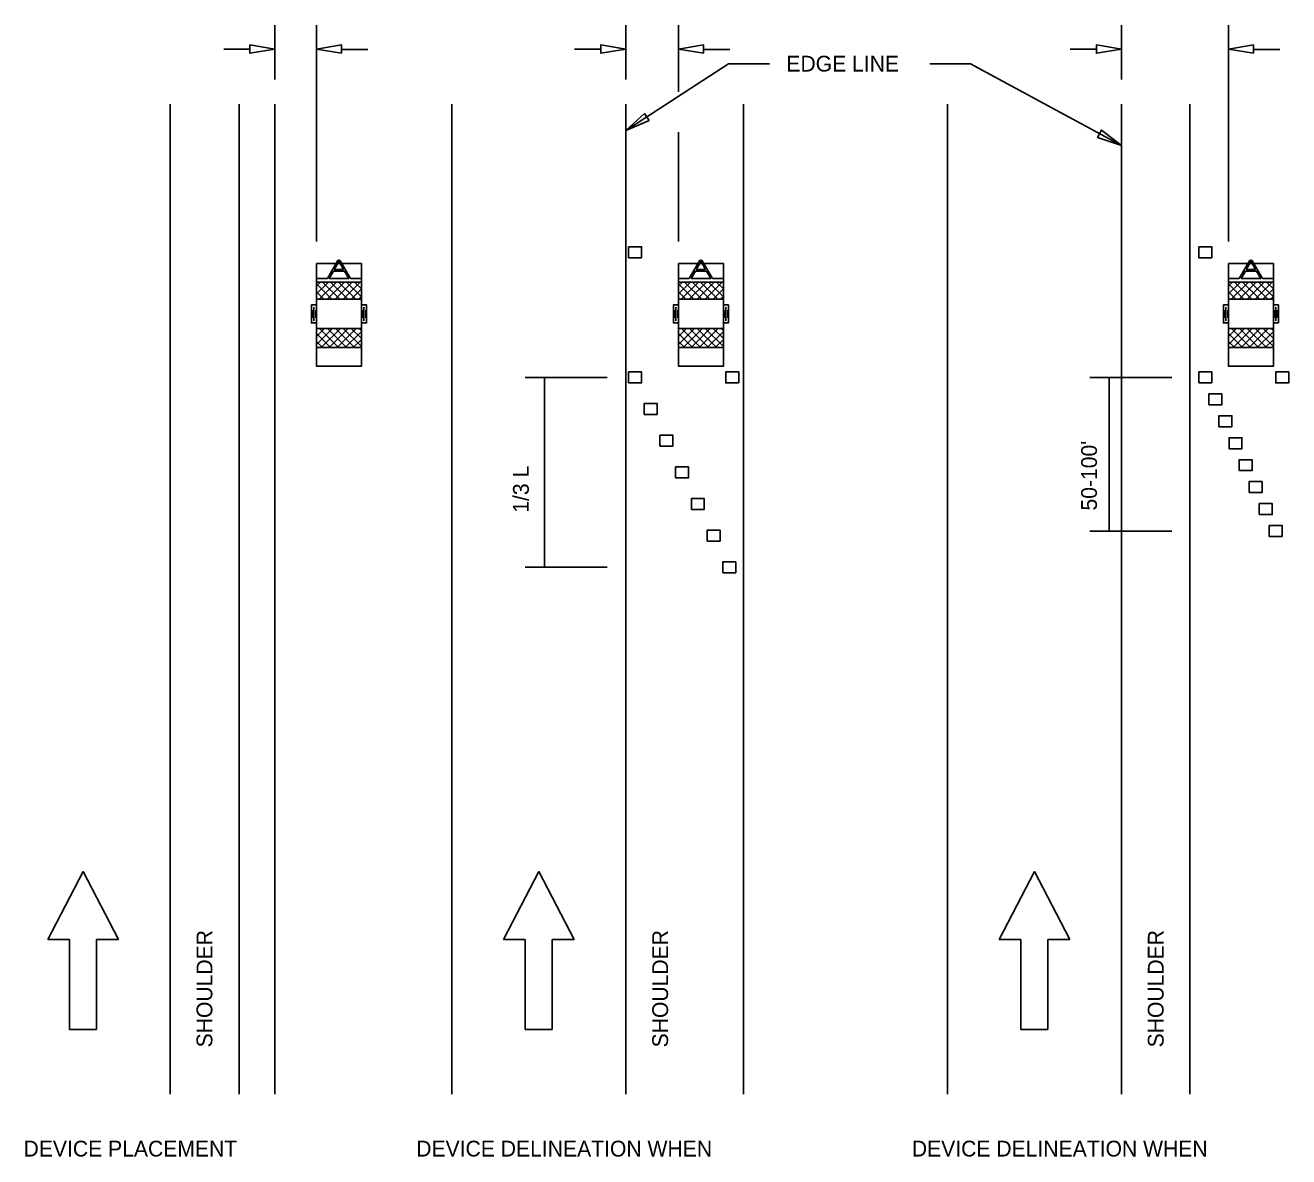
# Model space of a CAD drawing. Extents: x 9 to 25.8, y 6 to 22.7.
# Drawn here: x 14.484 to 19.447, y 11.055 to 15.5 of the extents above; entities that cross this region are included whole.
import ezdxf

# ---------------------------------------------------------------- set-up
doc = ezdxf.new("R2010")
doc.units = 0
for name, color, linetype in [('C-SIGN-FACE_N', 7, 'Continuous'), ('DETL-DIMS', 7, 'Continuous'), ('DETL-LINE', 7, 'Continuous'), ('DETL-NOTE', 7, 'Continuous'), ('SIGN-FACE_P', 7, 'Continuous'), ('SIGN-POST_VSL', 7, 'Continuous'), ('TRAF-MISC', 7, 'Continuous'), ('USER-BORD', 7, 'Continuous')]:
    doc.layers.add(name, color=color, linetype=linetype)

# ---------------------------------------------------------------- blocks, each defined once
blk = doc.blocks.new('DIR2')
at = {"layer": 'USER-BORD'}
for p, q in [((0, 0.0001), (-0.0034, -0.0048)), ((0, 0.0001), (0.0034, -0.0048)), ((-0.0034, -0.0048), (-0.0013, -0.0048)), ((-0.0013, -0.0113), (-0.0013, -0.0048)), ((0.0034, -0.0048), (0.0013, -0.0048)), ((0.0013, -0.0113), (0.0013, -0.0048)), ((-0.0001, -0.0113), (-0.0013, -0.0113)), ((-0.0001, -0.0113), (0.0001, -0.0113)), ((0.0001, -0.0113), (0.0013, -0.0113))]:
    blk.add_line(p, q, dxfattribs=at)

msp = doc.modelspace()

# ---------------------------------------------------------------- linework, layer by layer
at = {"layer": 'C-SIGN-FACE_N'}
for points in [[(15.6282, 14.4912), (15.8043, 14.4912), (15.8043, 14.2335), (15.6282, 14.2335)], [(17.0501, 14.4912), (17.2262, 14.4912), (17.2262, 14.2335), (17.0501, 14.2335)], [(19.2106, 14.4912), (19.3868, 14.4912), (19.3868, 14.2335), (19.2106, 14.2335)]]:
    msp.add_lwpolyline(points, close=True, dxfattribs=at)
at = {"layer": 'DETL-DIMS'}
for p, q in [((15.4647, 15.2868), (15.4647, 15.4998)), ((15.6281, 14.6498), (15.6281, 15.4999)), ((16.8432, 15.2868), (16.8432, 15.4998)), ((17.0501, 15.2388), (17.0501, 15.4999)), ((18.7901, 15.2868), (18.7901, 15.4998)), ((19.2106, 14.6498), (19.2106, 15.4999)), ((15.3667, 15.4065), (15.2633, 15.4065)), ((15.8294, 15.4046), (15.7259, 15.4046)), ((16.7452, 15.4065), (16.6417, 15.4065)), ((17.2513, 15.4046), (17.1479, 15.4046)), ((18.692, 15.4065), (18.5886, 15.4065)), ((19.4119, 15.4046), (19.3084, 15.4046)), ((17.2468, 15.349), (16.8432, 15.086)), ((17.4071, 15.349), (17.2468, 15.349)), ((18.0373, 15.349), (18.1976, 15.349)), ((18.1976, 15.349), (18.7901, 15.0271)), ((17.0501, 14.6498), (17.0501, 15.0799)), ((16.77, 14.1165), (16.4483, 14.1165)), ((16.5241, 14.1165), (16.5241, 13.3704)), ((18.988, 14.1165), (18.6662, 14.1165)), ((18.7421, 14.1165), (18.7421, 13.5129)), ((18.988, 13.5129), (18.6662, 13.5129)), ((16.77, 13.3704), (16.4483, 13.3704))]:
    msp.add_line(p, q, dxfattribs=at)
for points in [[(15.3667, 15.4228), (15.3667, 15.3902), (15.4647, 15.4065)], [(15.7262, 15.3903), (15.7262, 15.4229), (15.6281, 15.4066)], [(16.7452, 15.4228), (16.7452, 15.3902), (16.8432, 15.4065)], [(17.1481, 15.3903), (17.1481, 15.4229), (17.0501, 15.4066)], [(18.692, 15.4228), (18.692, 15.3902), (18.7901, 15.4065)], [(19.3087, 15.3903), (19.3087, 15.4229), (19.2106, 15.4066)], [(16.9342, 15.1258), (16.9164, 15.1532), (16.8432, 15.086)], [(18.6961, 15.0595), (18.7117, 15.0882), (18.7901, 15.0271)]]:
    msp.add_lwpolyline(points, close=True, dxfattribs=at)
at = {"layer": 'DETL-LINE'}
for p, q in [((15.0531, 15.1901), (15.0531, 11.3001)), ((15.3246, 15.1901), (15.3246, 11.3001)), ((15.4647, 11.3001), (15.4647, 15.1901)), ((16.1595, 15.1901), (16.1595, 11.3001)), ((16.8432, 15.1901), (16.8432, 11.3001)), ((17.305, 15.1901), (17.305, 11.3001)), ((18.1063, 15.1901), (18.1063, 11.3001)), ((18.7901, 15.1901), (18.7901, 11.3001)), ((19.0594, 15.1901), (19.0594, 11.3001))]:
    msp.add_line(p, q, dxfattribs=at)
for points in [[(16.8539, 14.6296), (16.8539, 14.5867), (16.9048, 14.5867), (16.9048, 14.6296)], [(19.094, 14.6296), (19.094, 14.5867), (19.145, 14.5867), (19.145, 14.6296)], [(16.8539, 14.095), (16.8539, 14.1379), (16.9048, 14.1379), (16.9048, 14.095)], [(17.2868, 14.095), (17.2868, 14.1379), (17.2358, 14.1379), (17.2358, 14.095)], [(19.094, 14.095), (19.094, 14.1379), (19.145, 14.1379), (19.145, 14.095)], [(19.4473, 14.095), (19.4473, 14.1379), (19.3963, 14.1379), (19.3963, 14.095)], [(19.1336, 14.0088), (19.1336, 14.0517), (19.1845, 14.0517), (19.1845, 14.0088)], [(16.9155, 13.9707), (16.9155, 14.0136), (16.9665, 14.0136), (16.9665, 13.9707)], [(19.1731, 13.9226), (19.1731, 13.9655), (19.2241, 13.9655), (19.2241, 13.9226)], [(16.9772, 13.8463), (16.9772, 13.8892), (17.0281, 13.8892), (17.0281, 13.8463)], [(19.2127, 13.8364), (19.2127, 13.8792), (19.2636, 13.8792), (19.2636, 13.8364)], [(17.0388, 13.722), (17.0388, 13.7649), (17.0898, 13.7649), (17.0898, 13.722)], [(19.2522, 13.7501), (19.2522, 13.793), (19.3032, 13.793), (19.3032, 13.7501)], [(19.2918, 13.6639), (19.2918, 13.7068), (19.3427, 13.7068), (19.3427, 13.6639)], [(17.1005, 13.5977), (17.1005, 13.6405), (17.1514, 13.6405), (17.1514, 13.5977)], [(19.3313, 13.5777), (19.3313, 13.6206), (19.3822, 13.6206), (19.3822, 13.5777)], [(17.1621, 13.4733), (17.1621, 13.5162), (17.2131, 13.5162), (17.2131, 13.4733)], [(19.3709, 13.4915), (19.3709, 13.5344), (19.4218, 13.5344), (19.4218, 13.4915)], [(17.2238, 13.349), (17.2238, 13.3918), (17.2747, 13.3918), (17.2747, 13.349)]]:
    msp.add_lwpolyline(points, close=True, dxfattribs=at)
at = {"layer": 'SIGN-FACE_P'}
for p, q in [((15.6282, 14.5044), (15.6282, 14.4912)), ((15.8043, 14.5044), (15.8043, 14.4912)), ((17.0501, 14.5044), (17.0501, 14.4912)), ((17.2262, 14.5044), (17.2262, 14.4912)), ((19.2107, 14.5044), (19.2107, 14.4912)), ((19.3868, 14.5044), (19.3868, 14.4912))]:
    msp.add_line(p, q, dxfattribs=at)
at = {"layer": 'SIGN-POST_VSL'}
for points in [[(15.6281, 14.5643), (15.8043, 14.5643), (15.8043, 14.1603), (15.6282, 14.1603)], [(17.0501, 14.5643), (17.2262, 14.5643), (17.2262, 14.1603), (17.0501, 14.1603)], [(19.2106, 14.5643), (19.3868, 14.5643), (19.3868, 14.1603), (19.2106, 14.1603)]]:
    msp.add_lwpolyline(points, close=True, dxfattribs=at)
at = {"layer": 'TRAF-MISC'}
for p, q in [((15.6706, 14.5044), (15.7111, 14.5746)), ((15.6978, 14.5397), (15.7133, 14.5665)), ((15.7346, 14.5397), (15.7192, 14.5665)), ((15.7619, 14.5044), (15.7213, 14.5746)), ((17.0925, 14.5044), (17.1331, 14.5746)), ((17.1198, 14.5397), (17.1352, 14.5665)), ((17.1566, 14.5397), (17.1411, 14.5665)), ((17.1838, 14.5044), (17.1433, 14.5746)), ((19.2531, 14.5044), (19.2936, 14.5746)), ((19.2803, 14.5397), (19.2958, 14.5665)), ((19.3171, 14.5397), (19.3017, 14.5665)), ((19.3444, 14.5044), (19.3038, 14.5746)), ((15.6282, 14.5044), (15.6706, 14.5044)), ((15.6774, 14.5044), (15.6944, 14.5338)), ((15.6774, 14.5044), (15.7551, 14.5044)), ((15.6944, 14.5338), (15.738, 14.5338)), ((15.6978, 14.5397), (15.7346, 14.5397)), ((15.7551, 14.5044), (15.738, 14.5338)), ((15.7619, 14.5044), (15.8043, 14.5044)), ((17.0501, 14.5044), (17.0925, 14.5044)), ((17.0993, 14.5044), (17.1164, 14.5338)), ((17.0993, 14.5044), (17.177, 14.5044)), ((17.1164, 14.5338), (17.16, 14.5338)), ((17.1198, 14.5397), (17.1566, 14.5397)), ((17.177, 14.5044), (17.16, 14.5338)), ((17.1838, 14.5044), (17.2262, 14.5044)), ((19.2107, 14.5044), (19.2531, 14.5044)), ((19.2599, 14.5044), (19.2769, 14.5338)), ((19.2599, 14.5044), (19.3376, 14.5044)), ((19.2769, 14.5338), (19.3205, 14.5338)), ((19.2803, 14.5397), (19.3171, 14.5397)), ((19.3376, 14.5044), (19.3205, 14.5338)), ((19.3444, 14.5044), (19.3868, 14.5044)), ((15.6282, 14.4912), (15.6282, 14.4236)), ((15.6282, 14.4444), (15.6749, 14.4912)), ((15.6282, 14.4757), (15.6436, 14.4912)), ((15.6282, 14.4839), (15.6884, 14.4236)), ((15.6282, 14.4526), (15.6572, 14.4236)), ((15.6386, 14.4236), (15.7061, 14.4912)), ((15.6521, 14.4912), (15.7197, 14.4236)), ((15.6698, 14.4236), (15.7374, 14.4912)), ((15.6834, 14.4912), (15.7509, 14.4236)), ((15.7011, 14.4236), (15.7686, 14.4912)), ((15.7146, 14.4912), (15.7822, 14.4236)), ((15.7323, 14.4236), (15.7999, 14.4912)), ((15.7459, 14.4912), (15.8043, 14.4328)), ((15.7636, 14.4236), (15.8043, 14.4643)), ((15.7772, 14.4912), (15.8043, 14.4641)), ((17.0501, 14.4912), (17.0501, 14.4236)), ((17.0501, 14.4444), (17.0969, 14.4912)), ((17.0501, 14.4757), (17.0656, 14.4912)), ((17.0501, 14.4839), (17.1104, 14.4236)), ((17.0501, 14.4526), (17.0792, 14.4236)), ((17.0606, 14.4236), (17.1281, 14.4912)), ((17.0741, 14.4912), (17.1417, 14.4236)), ((17.0918, 14.4236), (17.1594, 14.4912)), ((17.1054, 14.4912), (17.1729, 14.4236)), ((17.1231, 14.4236), (17.1906, 14.4912)), ((17.1366, 14.4912), (17.2042, 14.4236)), ((17.1543, 14.4236), (17.2219, 14.4912)), ((17.1679, 14.4912), (17.2262, 14.4328)), ((17.1856, 14.4236), (17.2262, 14.4643)), ((17.1991, 14.4912), (17.2262, 14.4641)), ((19.2106, 14.4912), (19.2106, 14.4236)), ((19.2106, 14.4444), (19.2574, 14.4912)), ((19.2106, 14.4757), (19.2261, 14.4912)), ((19.2106, 14.4839), (19.2709, 14.4236)), ((19.2106, 14.4526), (19.2397, 14.4236)), ((19.2211, 14.4236), (19.2886, 14.4912)), ((19.2346, 14.4912), (19.3022, 14.4236)), ((19.2523, 14.4236), (19.3199, 14.4912)), ((19.2659, 14.4912), (19.3334, 14.4236)), ((19.2836, 14.4236), (19.3511, 14.4912)), ((19.2971, 14.4912), (19.3647, 14.4236)), ((19.3148, 14.4236), (19.3824, 14.4912)), ((19.3284, 14.4912), (19.3868, 14.4328)), ((19.3461, 14.4236), (19.3868, 14.4643)), ((19.3596, 14.4912), (19.3868, 14.4641)), ((15.6282, 14.4236), (15.8043, 14.4236)), ((15.7949, 14.4236), (15.8043, 14.433)), ((17.0501, 14.4236), (17.2262, 14.4236)), ((17.2168, 14.4236), (17.2262, 14.433)), ((19.2106, 14.4236), (19.3868, 14.4236)), ((19.3773, 14.4236), (19.3868, 14.433)), ((15.6112, 14.381), (15.6112, 14.351)), ((15.6181, 14.3926), (15.6181, 14.3393)), ((15.625, 14.381), (15.625, 14.351)), ((15.8074, 14.381), (15.8074, 14.351)), ((15.8143, 14.3926), (15.8143, 14.3393)), ((15.8212, 14.381), (15.8212, 14.351)), ((17.0332, 14.381), (17.0332, 14.351)), ((17.0401, 14.3926), (17.0401, 14.3393)), ((17.047, 14.381), (17.047, 14.351)), ((17.2294, 14.381), (17.2294, 14.351)), ((17.2363, 14.3926), (17.2363, 14.3393)), ((17.2432, 14.381), (17.2432, 14.351)), ((19.1937, 14.381), (19.1937, 14.351)), ((19.2006, 14.3926), (19.2006, 14.3393)), ((19.2075, 14.381), (19.2075, 14.351)), ((19.3899, 14.381), (19.3899, 14.351)), ((19.3968, 14.3926), (19.3968, 14.3393)), ((19.4037, 14.381), (19.4037, 14.351)), ((15.8043, 14.3083), (15.6282, 14.3083)), ((15.6282, 14.246), (15.6904, 14.3083)), ((15.6282, 14.2773), (15.6592, 14.3083)), ((15.6395, 14.3083), (15.7144, 14.2335)), ((15.6468, 14.2335), (15.7217, 14.3083)), ((15.6708, 14.3083), (15.7456, 14.2335)), ((15.6781, 14.2335), (15.7529, 14.3083)), ((15.702, 14.3083), (15.7769, 14.2335)), ((15.7094, 14.2335), (15.7842, 14.3083)), ((15.7333, 14.3083), (15.8043, 14.2373)), ((15.7406, 14.2335), (15.8043, 14.2971)), ((15.7645, 14.3083), (15.8043, 14.2686)), ((15.7958, 14.3083), (15.8043, 14.2999)), ((15.8043, 14.2335), (15.8043, 14.3083)), ((17.2262, 14.3083), (17.0501, 14.3083)), ((17.0501, 14.246), (17.1124, 14.3083)), ((17.0501, 14.2773), (17.0812, 14.3083)), ((17.0615, 14.3083), (17.1363, 14.2335)), ((17.0688, 14.2335), (17.1437, 14.3083)), ((17.0928, 14.3083), (17.1676, 14.2335)), ((17.1001, 14.2335), (17.1749, 14.3083)), ((17.124, 14.3083), (17.1989, 14.2335)), ((17.1313, 14.2335), (17.2062, 14.3083)), ((17.1553, 14.3083), (17.2262, 14.2373)), ((17.1626, 14.2335), (17.2262, 14.2971)), ((17.1865, 14.3083), (17.2262, 14.2686)), ((17.2178, 14.3083), (17.2262, 14.2999)), ((17.2262, 14.2335), (17.2262, 14.3083)), ((19.3868, 14.3083), (19.2107, 14.3083)), ((19.2107, 14.246), (19.2729, 14.3083)), ((19.2107, 14.2773), (19.2417, 14.3083)), ((19.222, 14.3083), (19.2969, 14.2335)), ((19.2293, 14.2335), (19.3042, 14.3083)), ((19.2533, 14.3083), (19.3281, 14.2335)), ((19.2606, 14.2335), (19.3354, 14.3083)), ((19.2845, 14.3083), (19.3594, 14.2335)), ((19.2919, 14.2335), (19.3667, 14.3083)), ((19.3158, 14.3083), (19.3868, 14.2373)), ((19.3231, 14.2335), (19.3868, 14.2971)), ((19.347, 14.3083), (19.3868, 14.2686)), ((19.3783, 14.3083), (19.3868, 14.2999)), ((19.3868, 14.2335), (19.3868, 14.3083)), ((15.6282, 14.2884), (15.6831, 14.2335)), ((15.6282, 14.2572), (15.6519, 14.2335)), ((15.7719, 14.2335), (15.8043, 14.2659)), ((17.0501, 14.2884), (17.1051, 14.2335)), ((17.0501, 14.2572), (17.0738, 14.2335)), ((17.1938, 14.2335), (17.2262, 14.2659)), ((19.2107, 14.2884), (19.2656, 14.2335)), ((19.2107, 14.2572), (19.2343, 14.2335)), ((19.3544, 14.2335), (19.3868, 14.2659)), ((15.8031, 14.2335), (15.8043, 14.2346)), ((17.2251, 14.2335), (17.2262, 14.2346)), ((19.3856, 14.2335), (19.3868, 14.2346))]:
    msp.add_line(p, q, dxfattribs=at)
for points in [[(15.6282, 14.4912), (15.6282, 14.2335), (15.8043, 14.2335), (15.8043, 14.4912)], [(15.6282, 14.4912), (15.8043, 14.4912), (15.8043, 14.4236), (15.6282, 14.4236)], [(17.0501, 14.4912), (17.0501, 14.2335), (17.2263, 14.2335), (17.2262, 14.4912)], [(17.0501, 14.4912), (17.2262, 14.4912), (17.2262, 14.4236), (17.0501, 14.4236)], [(19.2106, 14.4912), (19.2107, 14.2335), (19.3868, 14.2335), (19.3868, 14.4912)], [(19.2106, 14.4912), (19.3868, 14.4912), (19.3868, 14.4236), (19.2106, 14.4236)], [(15.6282, 14.4015), (15.608, 14.4015), (15.608, 14.3304), (15.6282, 14.3304)], [(15.8043, 14.4015), (15.8244, 14.4015), (15.8244, 14.3304), (15.8043, 14.3304)], [(17.0501, 14.4015), (17.03, 14.4015), (17.03, 14.3304), (17.0501, 14.3304)], [(17.2262, 14.4015), (17.2464, 14.4015), (17.2464, 14.3304), (17.2262, 14.3304)], [(19.2106, 14.4015), (19.1905, 14.4015), (19.1905, 14.3304), (19.2106, 14.3304)], [(19.3868, 14.4015), (19.4069, 14.4015), (19.4069, 14.3304), (19.3868, 14.3304)], [(15.6282, 14.3083), (15.8043, 14.3083), (15.8043, 14.2335), (15.6282, 14.2335)], [(17.0501, 14.3083), (17.2262, 14.3083), (17.2262, 14.2335), (17.0501, 14.2335)], [(19.2106, 14.3083), (19.3868, 14.3083), (19.3868, 14.2335), (19.2106, 14.2335)]]:
    msp.add_lwpolyline(points, close=True, dxfattribs=at)
for points in [[(15.8043, 14.4236), (15.8043, 14.4912), (15.6282, 14.4912)], [(17.2262, 14.4236), (17.2262, 14.4912), (17.0501, 14.4912)], [(19.3868, 14.4236), (19.3868, 14.4912), (19.2106, 14.4912)], [(15.6282, 14.3083), (15.6282, 14.2335), (15.8043, 14.2335)], [(17.0501, 14.3083), (17.0501, 14.2335), (17.2262, 14.2335)], [(19.2107, 14.3083), (19.2107, 14.2335), (19.3868, 14.2335)]]:
    msp.add_lwpolyline(points, dxfattribs=at)
for centre, radius in [((15.7162, 14.5716), 0.00589), ((15.7162, 14.5716), 0.00295), ((15.7162, 14.5716), 0.00177), ((17.1382, 14.5716), 0.00589), ((17.1382, 14.5716), 0.00295), ((17.1382, 14.5716), 0.00177), ((19.2987, 14.5716), 0.00589), ((19.2987, 14.5716), 0.00295), ((19.2987, 14.5716), 0.00177)]:
    msp.add_circle(centre, radius, dxfattribs=at)

# ---------------------------------------------------------------- block references
at = {"layer": 'DETL-LINE', "xscale": 40.80078878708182, "yscale": 54.4010517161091, "rotation": 1.0739341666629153e-12}
for p in [(14.7112, 12.1691), (16.5013, 12.1691), (18.4482, 12.1691)]:
    msp.add_blockref('DIR2', p, dxfattribs=at)

# ---------------------------------------------------------------- texts
at = {"layer": 'DETL-NOTE'}
for s, height, p in [('EDGE LINE', 0.06207, (17.4737, 15.318)), ('DEVICE PLACEMENT', 0.062069, (14.4771, 11.0554)), ('DEVICE DELINEATION WHEN', 0.062069, (16.0197, 11.0554)), ('DEVICE DELINEATION WHEN', 0.062069, (17.9666, 11.0554))]:
    msp.add_text(s, height=height, dxfattribs=at).set_placement(p)
for s, p in [("50-100'", (18.6939, 13.5933)), ('1/3 L', (16.462, 13.5846)), ('SHOULDER', (15.2188, 11.4841)), ('SHOULDER', (17.009, 11.4841)), ('SHOULDER', (18.9558, 11.4841))]:
    msp.add_text(s, height=0.06207, rotation=90, dxfattribs=at).set_placement(p)

doc.saveas('drawing.dxf')
